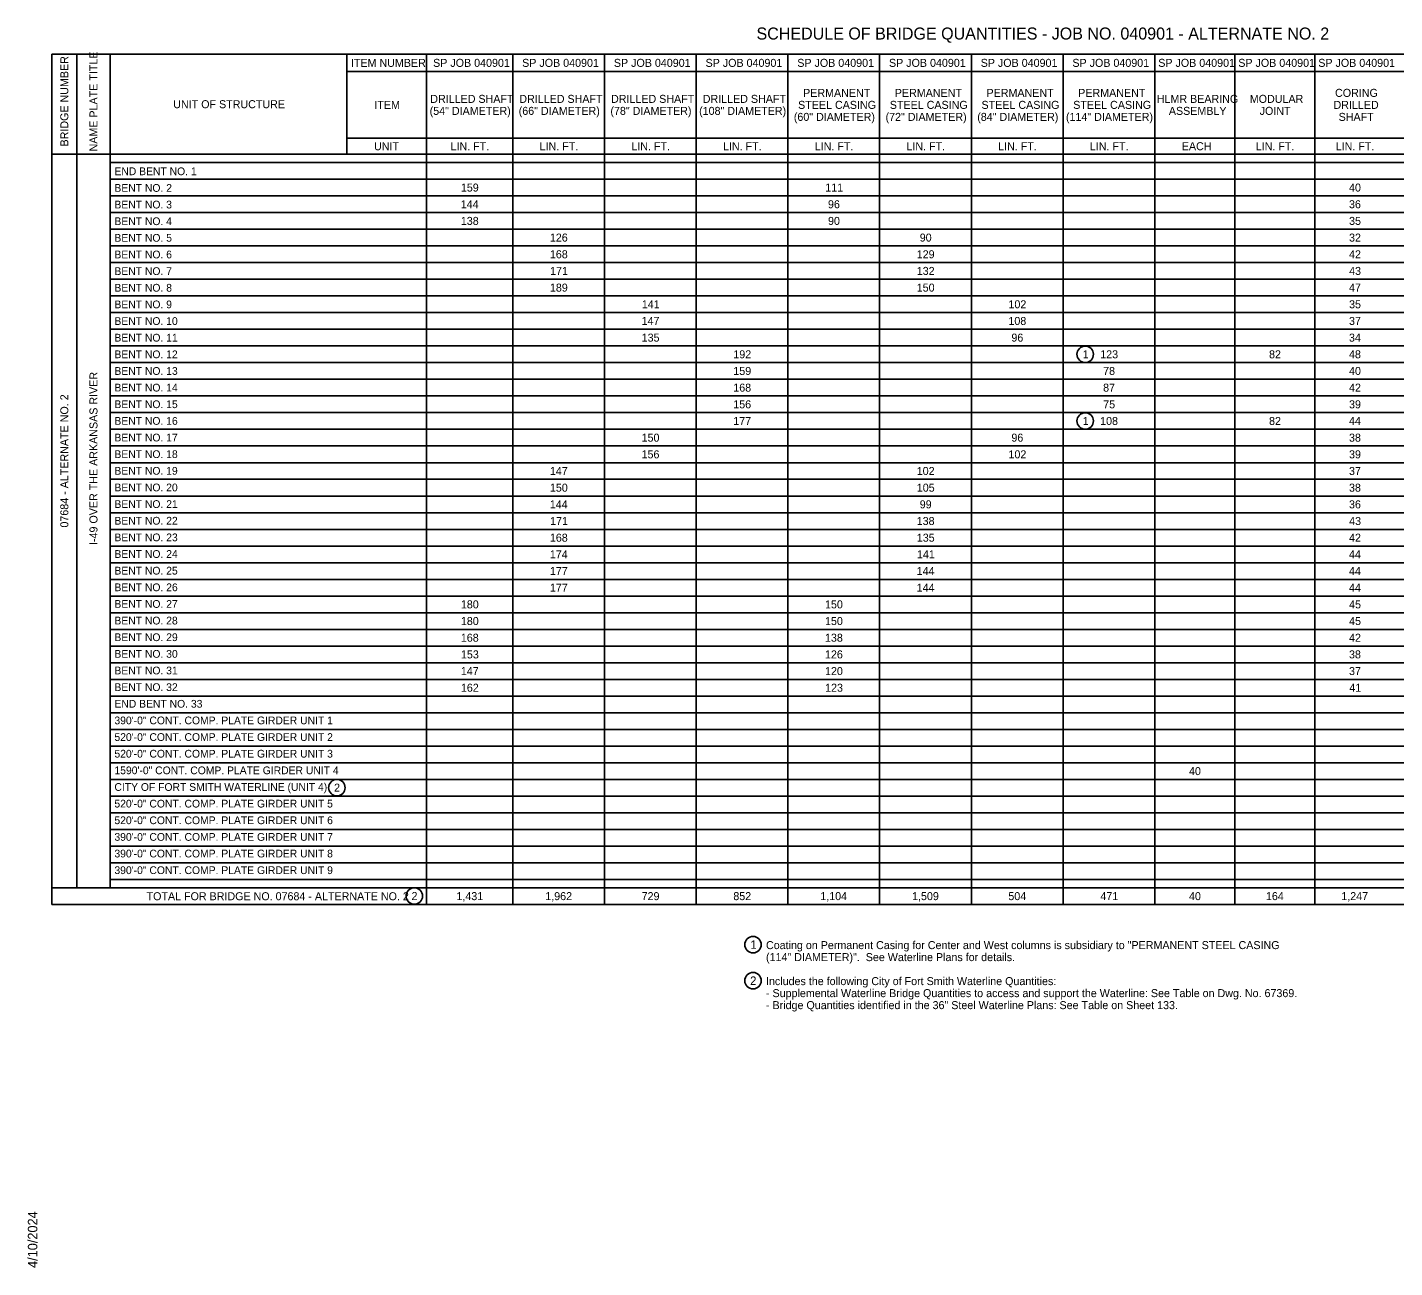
# Model space of a CAD drawing. Extents: x 0.06 to 1.36, y 0.04 to 0.85.
# Drawn here: x 0.06 to 0.914, y 0.079 to 0.854 of the extents above; entities that cross this region are included whole.
import ezdxf

# ---------------------------------------------------------------- set-up
doc = ezdxf.new("R2010")
doc.units = 0
for name, color, linetype in [('R_ROW', 7, 'Continuous'), ('R_Shade By Others', 7, 'Continuous'), ('R_Survey Control', 7, 'Continuous'), ('R_Wall', 7, 'Continuous')]:
    doc.layers.add(name, color=color, linetype=linetype)

msp = doc.modelspace()

# ---------------------------------------------------------------- linework, layer by layer
at = {"layer": 'R_Survey Control'}
for p, q in [((0.07508, 0.3057), (0.07508, 0.83695)), ((0.07508, 0.83695), (1.30054, 0.83695)), ((0.09071, 0.31612), (0.09071, 0.83695)), ((0.11154, 0.31612), (0.11154, 0.83695)), ((0.11154, 0.77445), (0.11154, 0.83695)), ((0.2593, 0.77445), (0.2593, 0.83695)), ((0.30915, 0.83695), (0.30915, 0.3057)), ((0.36311, 0.83695), (0.36311, 0.3057)), ((0.4204, 0.83695), (0.4204, 0.3057)), ((0.47769, 0.83695), (0.47769, 0.3057)), ((0.53498, 0.83695), (0.53498, 0.3057)), ((0.59227, 0.83695), (0.59227, 0.3057)), ((0.64957, 0.83695), (0.64957, 0.3057)), ((0.70686, 0.83695), (0.70686, 0.3057)), ((0.76415, 0.83695), (0.76415, 0.3057)), ((0.81414, 0.83695), (0.81414, 0.3057)), ((0.86412, 0.83695), (0.86412, 0.3057)), ((0.2593, 0.78445), (1.30054, 0.78445)), ((0.07508, 0.77445), (1.30054, 0.77445)), ((0.11154, 0.76924), (1.30054, 0.76924)), ((0.11154, 0.75883), (1.30054, 0.75883)), ((0.11154, 0.74841), (1.30054, 0.74841)), ((0.11154, 0.73799), (1.30054, 0.73799)), ((0.11154, 0.72758), (1.30054, 0.72758)), ((0.11154, 0.71716), (1.30054, 0.71716)), ((0.11154, 0.70674), (1.30054, 0.70674)), ((0.11154, 0.69633), (1.30054, 0.69633)), ((0.11154, 0.68591), (1.30054, 0.68591)), ((0.11154, 0.67549), (1.30054, 0.67549)), ((0.11154, 0.66508), (1.30054, 0.66508)), ((0.11154, 0.65466), (1.30054, 0.65466)), ((0.11154, 0.64424), (1.30054, 0.64424)), ((0.11154, 0.63383), (1.30054, 0.63383)), ((0.11154, 0.62341), (1.30054, 0.62341)), ((0.11154, 0.61299), (1.30054, 0.61299)), ((0.11154, 0.60258), (1.30054, 0.60258)), ((0.11154, 0.59216), (1.30054, 0.59216)), ((0.11154, 0.58174), (1.30054, 0.58174)), ((0.11154, 0.57133), (1.30054, 0.57133)), ((0.11154, 0.56091), (1.30054, 0.56091)), ((0.11154, 0.55049), (1.30054, 0.55049)), ((0.11154, 0.54008), (1.30054, 0.54008)), ((0.11154, 0.52966), (1.30054, 0.52966)), ((0.11154, 0.51924), (1.30054, 0.51924)), ((0.11154, 0.50883), (1.30054, 0.50883)), ((0.11154, 0.49841), (1.30054, 0.49841)), ((0.11154, 0.48799), (1.30054, 0.48799)), ((0.11154, 0.47758), (1.30054, 0.47758)), ((0.11154, 0.46716), (1.30054, 0.46716)), ((0.11154, 0.45674), (1.30054, 0.45674)), ((0.11154, 0.44633), (1.30054, 0.44633)), ((0.11154, 0.43591), (1.30054, 0.43591)), ((0.11154, 0.42549), (1.30054, 0.42549)), ((0.11154, 0.41508), (1.30054, 0.41508)), ((0.11154, 0.40466), (1.30054, 0.40466)), ((0.11154, 0.39424), (1.30054, 0.39424)), ((0.11154, 0.38383), (1.30054, 0.38383)), ((0.11154, 0.37341), (1.30054, 0.37341)), ((0.11154, 0.36299), (1.30054, 0.36299)), ((0.11154, 0.35258), (1.30054, 0.35258)), ((0.11154, 0.34216), (1.30054, 0.34216)), ((0.11154, 0.33174), (1.30054, 0.33174)), ((0.07508, 0.31612), (1.30054, 0.31612)), ((0.11154, 0.32133), (1.30054, 0.32133)), ((0.07508, 0.3057), (1.30054, 0.3057))]:
    msp.add_line(p, q, dxfattribs=at)
msp.add_lwpolyline([(0.2593, 0.82612), (0.30758, 0.82612), (0.36154, 0.82612), (0.40321, 0.82612), (0.44487, 0.82612), (0.49175, 0.82612), (0.52821, 0.82612), (0.58029, 0.82612), (0.64019, 0.82612), (0.7079, 0.82612), (0.75998, 0.82612), (0.81206, 0.82612), (0.85894, 0.82612), (0.86623, 0.82612), (0.92873, 0.82612), (0.99644, 0.82612), (1.06415, 0.82612), (1.11623, 0.82612), (1.16831, 0.82612), (1.30054, 0.82612)], dxfattribs=at)
at = {"layer": 'R_Wall'}
for p, q in [((0.07508, 0.77445), (0.09071, 0.77445)), ((0.09071, 0.77445), (0.11154, 0.77445))]:
    msp.add_line(p, q, dxfattribs=at)
for centre in [(0.7207, 0.64945), (0.7207, 0.60779), (0.25316, 0.37868), (0.30155, 0.31097), (0.51317, 0.28059), (0.51317, 0.25809)]:
    msp.add_circle(centre, 0.00515, dxfattribs=at)

# ---------------------------------------------------------------- texts
at = {"layer": 'R_ROW'}
msp.add_text('SCHEDULE OF BRIDGE QUANTITIES - JOB NO. 040901 - ALTERNATE NO. 2', height=0.0075, dxfattribs=at).set_placement((0.51531, 0.84612))
at = {"layer": 'R_Shade By Others'}
msp.add_text('4/10/2024', height=0.00595, rotation=89.99995, dxfattribs=at).set_placement((0.06607, 0.0786))
at = {"layer": 'R_Survey Control'}
for s, p in [('NAME PLATE TITLE', (0.10362, 0.77619)), ('BRIDGE NUMBER', (0.0854, 0.77929)), ('I-49 OVER THE ARKANSAS RIVER', (0.10362, 0.53031)), ('07684 - ALTERNATE NO. 2', (0.0854, 0.54119))]:
    msp.add_text(s, height=0.005, rotation=90, dxfattribs=at).set_placement(p)
for s, height, p in [('ITEM NUMBER', 0.005, (0.26194, 0.82904)), ('SP JOB 040901', 0.005, (0.3133, 0.82904)), ('SP JOB 040901', 0.005, (0.36892, 0.82904)), ('SP JOB 040901', 0.005, (0.42622, 0.82904)), ('SP JOB 040901', 0.005, (0.48351, 0.82904)), ('SP JOB 040901', 0.005, (0.5408, 0.82904)), ('SP JOB 040901', 0.005, (0.59809, 0.82904)), ('SP JOB 040901', 0.005, (0.65538, 0.82904)), ('SP JOB 040901', 0.005, (0.71267, 0.82904)), ('SP JOB 040901', 0.005, (0.76631, 0.82904)), ('SP JOB 040901', 0.005, (0.8163, 0.82904)), ('SP JOB 040901', 0.005, (0.86628, 0.82904)), ('DRILLED SHAFT', 0.005, (0.31153, 0.80654)), ('DRILLED SHAFT', 0.005, (0.36715, 0.80654)), ('DRILLED SHAFT', 0.005, (0.42444, 0.80654)), ('DRILLED SHAFT', 0.005, (0.48174, 0.80654)), ('PERMANENT', 0.005, (0.54443, 0.81029)), ('PERMANENT', 0.005, (0.60172, 0.81029)), ('PERMANENT', 0.005, (0.65901, 0.81029)), ('PERMANENT', 0.005, (0.71631, 0.81029)), ('HLMR BEARING', 0.005, (0.76539, 0.80654)), ('MODULAR', 0.005, (0.8235, 0.80654)), ('CORING', 0.005, (0.87677, 0.81029)), ('UNIT OF STRUCTURE', 0.005, (0.15095, 0.8032)), ('ITEM', 0.005, (0.27661, 0.80279)), ('(54" DIAMETER)', 0.005, (0.31114, 0.79904)), ('(66" DIAMETER)', 0.005, (0.36677, 0.79904)), ('(78" DIAMETER)', 0.005, (0.42406, 0.79904)), ('(108" DIAMETER)', 0.005, (0.47948, 0.79904)), ('STEEL CASING', 0.005, (0.54131, 0.80279)), ('STEEL CASING', 0.005, (0.59861, 0.80279)), ('STEEL CASING', 0.005, (0.6559, 0.80279)), ('STEEL CASING', 0.005, (0.71319, 0.80279)), ('ASSEMBLY', 0.005, (0.77293, 0.79904)), ('JOINT', 0.005, (0.82968, 0.79904)), ('DRILLED', 0.005, (0.87579, 0.80279)), ('(60" DIAMETER)', 0.005, (0.53864, 0.79529)), ('(72" DIAMETER)', 0.005, (0.59594, 0.79529)), ('(84" DIAMETER)', 0.005, (0.65323, 0.79529)), ('(114" DIAMETER)', 0.005, (0.70864, 0.79529)), ('SHAFT', 0.005, (0.87901, 0.79529)), ('UNIT', 0.005, (0.27638, 0.77695)), ('LIN. FT.', 0.005, (0.32421, 0.77695)), ('LIN. FT.', 0.005, (0.37983, 0.77695)), ('LIN. FT.', 0.005, (0.43712, 0.77695)), ('LIN. FT.', 0.005, (0.49441, 0.77695)), ('LIN. FT.', 0.005, (0.55171, 0.77695)), ('LIN. FT.', 0.005, (0.609, 0.77695)), ('LIN. FT.', 0.005, (0.66629, 0.77695)), ('LIN. FT.', 0.005, (0.72358, 0.77695)), ('EACH', 0.005, (0.78102, 0.77695)), ('LIN. FT.', 0.005, (0.82721, 0.77695)), ('LIN. FT.', 0.005, (0.87718, 0.77695)), ('END BENT NO. 1', 0.0048358, (0.11421, 0.76137)), ('BENT NO. 2', 0.004836, (0.11421, 0.75098)), ('159', 0.005, (0.33064, 0.75112)), ('111', 0.005, (0.55828, 0.75112)), ('40', 0.005, (0.8855, 0.75112)), ('BENT NO. 3', 0.004836, (0.11421, 0.74058)), ('144', 0.005, (0.33058, 0.7407)), ('96', 0.005, (0.55999, 0.7407)), ('36', 0.005, (0.88547, 0.7407)), ('BENT NO. 4', 0.004836, (0.11421, 0.73018)), ('138', 0.005, (0.33062, 0.73029)), ('90', 0.005, (0.56001, 0.73029)), ('35', 0.005, (0.88554, 0.73029)), ('BENT NO. 5', 0.004836, (0.11421, 0.71979)), ('126', 0.005, (0.38624, 0.71987)), ('90', 0.005, (0.61731, 0.71987)), ('32', 0.005, (0.88551, 0.71987)), ('BENT NO. 6', 0.004836, (0.11421, 0.70939)), ('168', 0.005, (0.38625, 0.70945)), ('129', 0.005, (0.61543, 0.70945)), ('42', 0.005, (0.88551, 0.70945)), ('BENT NO. 7', 0.004836, (0.11421, 0.69899)), ('171', 0.005, (0.3864, 0.69904)), ('132', 0.005, (0.61544, 0.69904)), ('43', 0.005, (0.88556, 0.69904)), ('BENT NO. 8', 0.004836, (0.11421, 0.6886)), ('189', 0.005, (0.38627, 0.68862)), ('150', 0.005, (0.61543, 0.68862)), ('47', 0.005, (0.88548, 0.68862)), ('BENT NO. 9', 0.004836, (0.11421, 0.6782)), ('141', 0.005, (0.44369, 0.6782)), ('102', 0.005, (0.67274, 0.6782)), ('35', 0.005, (0.88554, 0.6782)), ('BENT NO. 10', 0.0048358, (0.11421, 0.6678)), ('147', 0.005, (0.44354, 0.66779)), ('108', 0.005, (0.67271, 0.66779)), ('37', 0.005, (0.88548, 0.66779)), ('BENT NO. 11', 0.0048358, (0.11421, 0.65741)), ('135', 0.005, (0.44359, 0.65737)), ('96', 0.005, (0.67457, 0.65737)), ('34', 0.005, (0.88545, 0.65737)), ('BENT NO. 12', 0.0048358, (0.11421, 0.64701)), ('192', 0.005, (0.50086, 0.64695)), ('123', 0.005, (0.73007, 0.64695)), ('82', 0.005, (0.83553, 0.64695)), ('48', 0.005, (0.88548, 0.64695)), ('BENT NO. 13', 0.0048358, (0.11421, 0.63661)), ('159', 0.005, (0.50085, 0.63654)), ('78', 0.005, (0.73187, 0.63654)), ('40', 0.005, (0.8855, 0.63654)), ('BENT NO. 14', 0.0048358, (0.11421, 0.62621)), ('168', 0.005, (0.50083, 0.62612)), ('87', 0.005, (0.73187, 0.62612)), ('42', 0.005, (0.88551, 0.62612)), ('BENT NO. 15', 0.0048358, (0.11421, 0.61582)), ('156', 0.005, (0.50082, 0.6157)), ('75', 0.005, (0.73193, 0.6157)), ('39', 0.005, (0.8855, 0.6157)), ('BENT NO. 16', 0.0048358, (0.11421, 0.60542)), ('177', 0.005, (0.50083, 0.60529)), ('108', 0.005, (0.73, 0.60529)), ('82', 0.005, (0.83553, 0.60529)), ('44', 0.005, (0.88545, 0.60529)), ('BENT NO. 17', 0.0048358, (0.11421, 0.59502)), ('150', 0.005, (0.44355, 0.59487)), ('96', 0.005, (0.67457, 0.59487)), ('38', 0.005, (0.88548, 0.59487)), ('BENT NO. 18', 0.0048358, (0.11421, 0.58463)), ('156', 0.005, (0.44353, 0.58445)), ('102', 0.005, (0.67274, 0.58445)), ('39', 0.005, (0.8855, 0.58445)), ('BENT NO. 19', 0.0048358, (0.11421, 0.57423)), ('147', 0.005, (0.38625, 0.57404)), ('102', 0.005, (0.61544, 0.57404)), ('37', 0.005, (0.88548, 0.57404)), ('BENT NO. 20', 0.0048358, (0.11421, 0.56383)), ('150', 0.005, (0.38626, 0.56362)), ('105', 0.005, (0.61547, 0.56362)), ('38', 0.005, (0.88548, 0.56362)), ('BENT NO. 21', 0.0048358, (0.11421, 0.55344)), ('144', 0.005, (0.38621, 0.5532)), ('99', 0.005, (0.61731, 0.5532)), ('36', 0.005, (0.88547, 0.5532)), ('BENT NO. 22', 0.0048358, (0.11421, 0.54304)), ('171', 0.005, (0.3864, 0.54279)), ('138', 0.005, (0.61541, 0.54279)), ('43', 0.005, (0.88556, 0.54279)), ('BENT NO. 23', 0.0048358, (0.11421, 0.53264)), ('168', 0.005, (0.38625, 0.53237)), ('135', 0.005, (0.61547, 0.53237)), ('42', 0.005, (0.88551, 0.53237)), ('BENT NO. 24', 0.0048358, (0.11421, 0.52225)), ('174', 0.005, (0.38621, 0.52195)), ('141', 0.005, (0.61557, 0.52195)), ('44', 0.005, (0.88545, 0.52195)), ('BENT NO. 25', 0.0048358, (0.11421, 0.51185)), ('177', 0.005, (0.38625, 0.51154)), ('144', 0.005, (0.61538, 0.51154)), ('44', 0.005, (0.88545, 0.51154)), ('BENT NO. 26', 0.0048358, (0.11421, 0.50145)), ('177', 0.005, (0.38625, 0.50112)), ('144', 0.005, (0.61538, 0.50112)), ('44', 0.005, (0.88545, 0.50112)), ('BENT NO. 27', 0.0048358, (0.11421, 0.49105)), ('180', 0.005, (0.33064, 0.4907)), ('150', 0.005, (0.55814, 0.4907)), ('45', 0.005, (0.88554, 0.4907)), ('BENT NO. 28', 0.0048358, (0.11421, 0.48066)), ('180', 0.005, (0.33064, 0.48029)), ('150', 0.005, (0.55814, 0.48029)), ('45', 0.005, (0.88554, 0.48029)), ('BENT NO. 29', 0.0048358, (0.11421, 0.47026)), ('168', 0.005, (0.33062, 0.46987)), ('138', 0.005, (0.55812, 0.46987)), ('42', 0.005, (0.88551, 0.46987)), ('BENT NO. 30', 0.0048358, (0.11421, 0.45986)), ('153', 0.005, (0.33069, 0.45945)), ('126', 0.005, (0.55811, 0.45945)), ('38', 0.005, (0.88548, 0.45945)), ('BENT NO. 31', 0.0048358, (0.11421, 0.44947)), ('147', 0.005, (0.33062, 0.44904)), ('120', 0.005, (0.55814, 0.44904)), ('37', 0.005, (0.88548, 0.44904)), ('BENT NO. 32', 0.0048358, (0.11421, 0.43907)), ('162', 0.005, (0.33065, 0.43862)), ('123', 0.005, (0.55819, 0.43862)), ('41', 0.005, (0.88564, 0.43862)), ('END BENT NO. 33', 0.0048358, (0.11421, 0.42867)), ('390\'-0" CONT. COMP. PLATE GIRDER UNIT 1', 0.0048358, (0.11421, 0.41828)), ('520\'-0" CONT. COMP. PLATE GIRDER UNIT 2', 0.0048358, (0.11421, 0.40788)), ('520\'-0" CONT. COMP. PLATE GIRDER UNIT 3', 0.0048358, (0.11421, 0.39748)), ('1590\'-0" CONT. COMP. PLATE GIRDER UNIT 4', 0.0048358, (0.11421, 0.38708)), ('40', 0.005, (0.78553, 0.38654)), ('CITY OF FORT SMITH WATERLINE (UNIT 4)', 0.0048358, (0.11421, 0.37669)), ('520\'-0" CONT. COMP. PLATE GIRDER UNIT 5', 0.0048358, (0.11421, 0.36629)), ('520\'-0" CONT. COMP. PLATE GIRDER UNIT 6', 0.0048358, (0.11421, 0.35589)), ('390\'-0" CONT. COMP. PLATE GIRDER UNIT 7', 0.0048358, (0.11421, 0.3455)), ('390\'-0" CONT. COMP. PLATE GIRDER UNIT 8', 0.0048358, (0.11421, 0.3351)), ('390\'-0" CONT. COMP. PLATE GIRDER UNIT 9', 0.0048358, (0.11421, 0.3247)), ('TOTAL FOR BRIDGE NO. 07684 - ALTERNATE NO. 2', 0.005, (0.13429, 0.30834)), ('1,431', 0.005, (0.32786, 0.30841)), ('1,962', 0.005, (0.38336, 0.30841)), ('729', 0.005, (0.44356, 0.30841)), ('852', 0.005, (0.50086, 0.30841)), ('1,104', 0.005, (0.55517, 0.30841)), ('1,509', 0.005, (0.61252, 0.30841)), ('504', 0.005, (0.67267, 0.30841)), ('471', 0.005, (0.73015, 0.30841)), ('40', 0.005, (0.78553, 0.30841)), ('164', 0.005, (0.83359, 0.30841)), ('1,247', 0.005, (0.88069, 0.30841))]:
    msp.add_text(s, height=height, dxfattribs=at).set_placement(p)
at = {"layer": 'R_Wall'}
for s, height, p in [('1', 0.005, (0.71911, 0.64695)), ('1', 0.005, (0.71911, 0.60529)), ('2', 0.005, (0.25143, 0.37618)), ('2', 0.005, (0.29982, 0.30847)), ('1', 0.00521, (0.51151, 0.27799)), ('Coating on Permanent Casing for Center and West columns is subsidiary to "PERMANENT STEEL CASING ', 0.005, (0.52126, 0.27781)), ('(114" DIAMETER)".  See Waterline Plans for details.', 0.005, (0.52126, 0.27031)), ('2', 0.00521, (0.51138, 0.25549)), ('Includes the following City of Fort Smith Waterline Quantities:', 0.005, (0.52126, 0.25531)), ('- Supplemental Waterline Bridge Quantities to access and support the Waterline: See Table on Dwg. No. 67369.', 0.005, (0.52126, 0.24781)), ('- Bridge Quantities identified in the 36" Steel Waterline Plans: See Table on Sheet 133.', 0.005, (0.52126, 0.24031))]:
    msp.add_text(s, height=height, dxfattribs=at).set_placement(p)

doc.saveas('drawing.dxf')
